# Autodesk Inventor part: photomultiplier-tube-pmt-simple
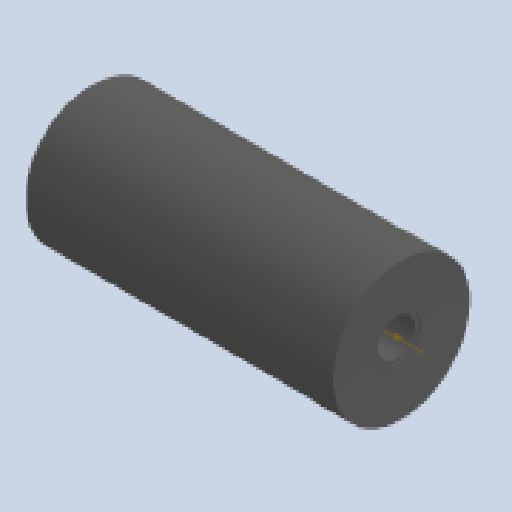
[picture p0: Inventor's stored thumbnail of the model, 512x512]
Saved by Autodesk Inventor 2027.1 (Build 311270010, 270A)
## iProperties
Created: 2026-07
Part Number: photomultiplier-tube-pmt-simple
Material: Generic
Document SubType Name: Modeling
Designer: dunge
Density: 1 g/cm^3
Appearance: Default
Author: dunge
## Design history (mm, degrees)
sketch "Sketch1"
  geometry: L1 (56.642, 13.97)-(56.642, 14.097); L2 (56.642, 14.097)-(64.262, 14.097); L3 (64.262, 14.097)-(64.262, 13.97); L4 (64.262, 13.97)-(63.5, 5.334); L5 (63.5, 5.334)-(63.5, 4.572); L6 (63.5, 4.572)-(63.246, 4.572); L7 (63.246, 4.572)-(63.246, 3.81); L8 (63.246, 3.81)-(2.54, 3.81); L9 (2.54, 3.81)-(2.54, 0); L10 (2.54, 0)-(0, 0); L11 (0, 0)-(0, 13.97); L12 (0, 13.97)-(56.642, 13.97); 1 further point
  constraints: 24 end point, 8 perpendicular, 1 coincident, 1 horizontal, 1 horizontal alignment, 1 parallel, 1 vertical
  dimensions: "d0" = 2.54 distance of L9.end L10.end; "d1" = 13.97 distance of L10.end L11.end; "d2" = 63.5 distance between parallel lines of L5 L11; "d3" = 0.254 distance between parallel lines of L5 L7; "d4" = 0.762 distance of L4.end L5.end; "d6" = 0.127 distance of L2.end L3.end; "d8" = 7.62 distance between parallel lines of L3 L1; "d9" = 3.81 distance of L8.end L9.end; "d10" = 0.762 distance of L6.end L7.end; "d12" = 0.762 distance between parallel lines of L5 L3
revolve "Revolution1" sketch "Sketch1" stored, may be unused: angle "d11" = 360 deg
workpoint "Work Point1"
  workaxis "Work Axis1"
chamfer "Chamfer1" distance "d13" = 1.27; stored, may be unused: second distance "d14" = 3.175, angle "d15" = 45 deg
body "Solid1"
node "Finishes"
node "Finish2" dims "Finish2_Area" = 829.05454
